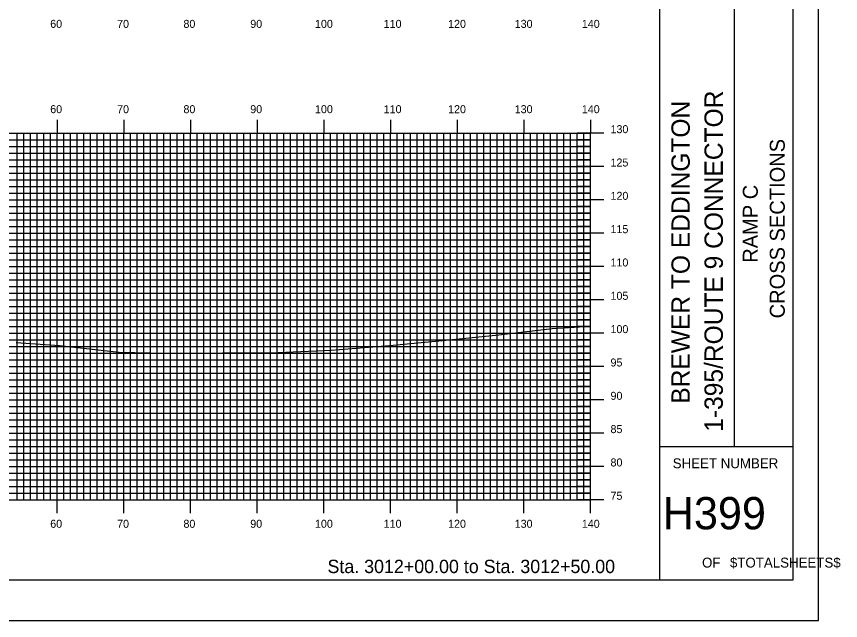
# Model space of a CAD drawing. Extents: x 1684012 to 1684355, y 461260 to 461480.
# Drawn here: x 1684231.6 to 1684355.2, y 461260 to 461350.6 of the extents above; entities that cross this region are included whole.
import ezdxf

# ---------------------------------------------------------------- set-up
doc = ezdxf.new("R2010")
doc.units = 0
for name, color, linetype in [('BORDER', 7, 'Continuous'), ('H_V ANNOTATION', 7, 'Continuous'), ('MAJOR', 7, 'Continuous'), ('MINOR', 7, 'Continuous'), ('PLOT BOUNDARY', 7, 'Continuous'), ('S_Roadway_Centerline', 7, 'Continuous')]:
    doc.layers.add(name, color=color, linetype=linetype)

msp = doc.modelspace()

# ---------------------------------------------------------------- linework, layer by layer
at = {"layer": 'BORDER'}
for p, q in [((1684328.09, 461266.07), (1684328.09, 461476.07)), ((1684339.27, 461286.08), (1684339.27, 461356.08)), ((1684328.09, 461286.08), (1684348.09, 461286.08))]:
    msp.add_line(p, q, dxfattribs=at)
msp.add_lwpolyline([(1684028.09, 461266.07), (1684348.09, 461266.07), (1684348.09, 461476.07), (1684028.09, 461476.07)], close=True, dxfattribs=at)
at = {"layer": 'MAJOR'}
for p, q in [((1684237.69, 461335.08), (1684237.69, 461333.07)), ((1684247.69, 461335.08), (1684247.69, 461333.07)), ((1684257.69, 461335.08), (1684257.69, 461333.07)), ((1684267.69, 461335.08), (1684267.69, 461333.07)), ((1684277.69, 461335.08), (1684277.69, 461333.07)), ((1684287.69, 461335.08), (1684287.69, 461333.07)), ((1684297.69, 461335.08), (1684297.69, 461333.07)), ((1684307.69, 461335.08), (1684307.69, 461333.07)), ((1684317.69, 461335.08), (1684317.69, 461333.07)), ((1684037.69, 461333.07), (1684317.69, 461333.07)), ((1684037.69, 461333.07), (1684317.69, 461333.07)), ((1684237.69, 461278.07), (1684237.69, 461333.07)), ((1684247.69, 461278.07), (1684247.69, 461333.07)), ((1684257.69, 461278.07), (1684257.69, 461333.07)), ((1684267.69, 461278.07), (1684267.69, 461333.07)), ((1684277.69, 461278.07), (1684277.69, 461333.07)), ((1684287.69, 461278.07), (1684287.69, 461333.07)), ((1684297.69, 461278.07), (1684297.69, 461333.07)), ((1684307.69, 461278.07), (1684307.69, 461333.07)), ((1684319.69, 461333.07), (1684315.69, 461333.07)), ((1684317.69, 461278.07), (1684317.69, 461333.07)), ((1684317.69, 461278.07), (1684317.69, 461333.07)), ((1684037.69, 461328.07), (1684317.69, 461328.07)), ((1684319.69, 461328.07), (1684315.69, 461328.07)), ((1684037.69, 461323.07), (1684317.69, 461323.07)), ((1684319.69, 461323.07), (1684315.69, 461323.07)), ((1684037.69, 461318.07), (1684317.69, 461318.07)), ((1684319.69, 461318.07), (1684315.69, 461318.07)), ((1684037.69, 461313.07), (1684317.69, 461313.07)), ((1684319.69, 461313.07), (1684315.69, 461313.07)), ((1684037.69, 461308.07), (1684317.69, 461308.07)), ((1684319.69, 461308.07), (1684315.69, 461308.07)), ((1684037.69, 461303.07), (1684317.69, 461303.07)), ((1684319.69, 461303.07), (1684315.69, 461303.07)), ((1684037.69, 461298.07), (1684317.69, 461298.07)), ((1684319.69, 461298.07), (1684315.69, 461298.07)), ((1684037.69, 461293.07), (1684317.69, 461293.07)), ((1684319.69, 461293.07), (1684315.69, 461293.07)), ((1684037.69, 461288.07), (1684317.69, 461288.07)), ((1684319.69, 461288.07), (1684315.69, 461288.07)), ((1684037.69, 461283.07), (1684317.69, 461283.07)), ((1684319.69, 461283.07), (1684315.69, 461283.07)), ((1684037.69, 461278.07), (1684317.69, 461278.07)), ((1684037.69, 461278.07), (1684317.69, 461278.07)), ((1684237.69, 461276.07), (1684237.69, 461278.07)), ((1684247.69, 461276.07), (1684247.69, 461278.07)), ((1684257.69, 461276.07), (1684257.69, 461278.07)), ((1684267.69, 461276.07), (1684267.69, 461278.07)), ((1684277.69, 461276.07), (1684277.69, 461278.07)), ((1684287.69, 461276.07), (1684287.69, 461278.07)), ((1684297.69, 461276.07), (1684297.69, 461278.07)), ((1684307.69, 461276.07), (1684307.69, 461278.07)), ((1684319.69, 461278.07), (1684315.69, 461278.07)), ((1684317.69, 461276.07), (1684317.69, 461278.07))]:
    msp.add_line(p, q, dxfattribs=at)
at = {"layer": 'MINOR'}
for p, q in [((1684231.69, 461278.07), (1684231.69, 461333.07)), ((1684232.69, 461278.07), (1684232.69, 461333.07)), ((1684233.69, 461278.07), (1684233.69, 461333.07)), ((1684234.69, 461278.07), (1684234.69, 461333.07)), ((1684235.69, 461278.07), (1684235.69, 461333.07)), ((1684236.69, 461278.07), (1684236.69, 461333.07)), ((1684238.69, 461278.07), (1684238.69, 461333.07)), ((1684239.69, 461278.07), (1684239.69, 461333.07)), ((1684240.69, 461278.07), (1684240.69, 461333.07)), ((1684241.69, 461278.07), (1684241.69, 461333.07)), ((1684242.69, 461278.07), (1684242.69, 461333.07)), ((1684243.69, 461278.07), (1684243.69, 461333.07)), ((1684244.69, 461278.07), (1684244.69, 461333.07)), ((1684245.69, 461278.07), (1684245.69, 461333.07)), ((1684246.69, 461278.07), (1684246.69, 461333.07)), ((1684248.69, 461278.07), (1684248.69, 461333.07)), ((1684249.69, 461278.07), (1684249.69, 461333.07)), ((1684250.69, 461278.07), (1684250.69, 461333.07)), ((1684251.69, 461278.07), (1684251.69, 461333.07)), ((1684252.69, 461278.07), (1684252.69, 461333.07)), ((1684253.69, 461278.07), (1684253.69, 461333.07)), ((1684254.69, 461278.07), (1684254.69, 461333.07)), ((1684255.69, 461278.07), (1684255.69, 461333.07)), ((1684256.69, 461278.07), (1684256.69, 461333.07)), ((1684258.69, 461278.07), (1684258.69, 461333.07)), ((1684259.69, 461278.07), (1684259.69, 461333.07)), ((1684260.69, 461278.07), (1684260.69, 461333.07)), ((1684261.69, 461278.07), (1684261.69, 461333.07)), ((1684262.69, 461278.07), (1684262.69, 461333.07)), ((1684263.69, 461278.07), (1684263.69, 461333.07)), ((1684264.69, 461278.07), (1684264.69, 461333.07)), ((1684265.69, 461278.07), (1684265.69, 461333.07)), ((1684266.69, 461278.07), (1684266.69, 461333.07)), ((1684268.69, 461278.07), (1684268.69, 461333.07)), ((1684269.69, 461278.07), (1684269.69, 461333.07)), ((1684270.69, 461278.07), (1684270.69, 461333.07)), ((1684271.69, 461278.07), (1684271.69, 461333.07)), ((1684272.69, 461278.07), (1684272.69, 461333.07)), ((1684273.69, 461278.07), (1684273.69, 461333.07)), ((1684274.69, 461278.07), (1684274.69, 461333.07)), ((1684275.69, 461278.07), (1684275.69, 461333.07)), ((1684276.69, 461278.07), (1684276.69, 461333.07)), ((1684278.69, 461278.07), (1684278.69, 461333.07)), ((1684279.69, 461278.07), (1684279.69, 461333.07)), ((1684280.69, 461278.07), (1684280.69, 461333.07)), ((1684281.69, 461278.07), (1684281.69, 461333.07)), ((1684282.69, 461278.07), (1684282.69, 461333.07)), ((1684283.69, 461278.07), (1684283.69, 461333.07)), ((1684284.69, 461278.07), (1684284.69, 461333.07)), ((1684285.69, 461278.07), (1684285.69, 461333.07)), ((1684286.69, 461278.07), (1684286.69, 461333.07)), ((1684288.69, 461278.07), (1684288.69, 461333.07)), ((1684289.69, 461278.07), (1684289.69, 461333.07)), ((1684290.69, 461278.07), (1684290.69, 461333.07)), ((1684291.69, 461278.07), (1684291.69, 461333.07)), ((1684292.69, 461278.07), (1684292.69, 461333.07)), ((1684293.69, 461278.07), (1684293.69, 461333.07)), ((1684294.69, 461278.07), (1684294.69, 461333.07)), ((1684295.69, 461278.07), (1684295.69, 461333.07)), ((1684296.69, 461278.07), (1684296.69, 461333.07)), ((1684298.69, 461278.07), (1684298.69, 461333.07)), ((1684299.69, 461278.07), (1684299.69, 461333.07)), ((1684300.69, 461278.07), (1684300.69, 461333.07)), ((1684301.69, 461278.07), (1684301.69, 461333.07)), ((1684302.69, 461278.07), (1684302.69, 461333.07)), ((1684303.69, 461278.07), (1684303.69, 461333.07)), ((1684304.69, 461278.07), (1684304.69, 461333.07)), ((1684305.69, 461278.07), (1684305.69, 461333.07)), ((1684306.69, 461278.07), (1684306.69, 461333.07)), ((1684308.69, 461278.07), (1684308.69, 461333.07)), ((1684309.69, 461278.07), (1684309.69, 461333.07)), ((1684310.69, 461278.07), (1684310.69, 461333.07)), ((1684311.69, 461278.07), (1684311.69, 461333.07)), ((1684312.69, 461278.07), (1684312.69, 461333.07)), ((1684313.69, 461278.07), (1684313.69, 461333.07)), ((1684314.69, 461278.07), (1684314.69, 461333.07)), ((1684315.69, 461278.07), (1684315.69, 461333.07)), ((1684316.69, 461278.07), (1684316.69, 461333.07)), ((1684037.69, 461332.07), (1684317.69, 461332.07)), ((1684317.69, 461332.07), (1684315.69, 461332.07)), ((1684037.69, 461331.07), (1684317.69, 461331.07)), ((1684317.69, 461331.07), (1684315.69, 461331.07)), ((1684037.69, 461330.07), (1684317.69, 461330.07)), ((1684317.69, 461330.07), (1684315.69, 461330.07)), ((1684037.69, 461329.07), (1684317.69, 461329.07)), ((1684317.69, 461329.07), (1684315.69, 461329.07)), ((1684037.69, 461327.07), (1684317.69, 461327.07)), ((1684317.69, 461327.07), (1684315.69, 461327.07)), ((1684037.69, 461326.07), (1684317.69, 461326.07)), ((1684317.69, 461326.07), (1684315.69, 461326.07)), ((1684037.69, 461325.07), (1684317.69, 461325.07)), ((1684317.69, 461325.07), (1684315.69, 461325.07)), ((1684037.69, 461324.07), (1684317.69, 461324.07)), ((1684317.69, 461324.07), (1684315.69, 461324.07)), ((1684037.69, 461322.07), (1684317.69, 461322.07)), ((1684317.69, 461322.07), (1684315.69, 461322.07)), ((1684037.69, 461321.07), (1684317.69, 461321.07)), ((1684317.69, 461321.07), (1684315.69, 461321.07)), ((1684037.69, 461320.07), (1684317.69, 461320.07)), ((1684317.69, 461320.07), (1684315.69, 461320.07)), ((1684037.69, 461319.07), (1684317.69, 461319.07)), ((1684317.69, 461319.07), (1684315.69, 461319.07)), ((1684037.69, 461317.07), (1684317.69, 461317.07)), ((1684317.69, 461317.07), (1684315.69, 461317.07)), ((1684037.69, 461316.07), (1684317.69, 461316.07)), ((1684317.69, 461316.07), (1684315.69, 461316.07)), ((1684037.69, 461315.07), (1684317.69, 461315.07)), ((1684317.69, 461315.07), (1684315.69, 461315.07)), ((1684037.69, 461314.07), (1684317.69, 461314.07)), ((1684317.69, 461314.07), (1684315.69, 461314.07)), ((1684037.69, 461312.07), (1684317.69, 461312.07)), ((1684317.69, 461312.07), (1684315.69, 461312.07)), ((1684037.69, 461311.07), (1684317.69, 461311.07)), ((1684317.69, 461311.07), (1684315.69, 461311.07)), ((1684037.69, 461310.07), (1684317.69, 461310.07)), ((1684317.69, 461310.07), (1684315.69, 461310.07)), ((1684037.69, 461309.07), (1684317.69, 461309.07)), ((1684317.69, 461309.07), (1684315.69, 461309.07)), ((1684037.69, 461307.07), (1684317.69, 461307.07)), ((1684317.69, 461307.07), (1684315.69, 461307.07)), ((1684037.69, 461306.07), (1684317.69, 461306.07)), ((1684317.69, 461306.07), (1684315.69, 461306.07)), ((1684037.69, 461305.07), (1684317.69, 461305.07)), ((1684317.69, 461305.07), (1684315.69, 461305.07)), ((1684037.69, 461304.07), (1684317.69, 461304.07)), ((1684317.69, 461304.07), (1684315.69, 461304.07)), ((1684037.69, 461302.07), (1684317.69, 461302.07)), ((1684317.69, 461302.07), (1684315.69, 461302.07)), ((1684037.69, 461301.07), (1684317.69, 461301.07)), ((1684317.69, 461301.07), (1684315.69, 461301.07)), ((1684037.69, 461300.07), (1684317.69, 461300.07)), ((1684317.69, 461300.07), (1684315.69, 461300.07)), ((1684037.69, 461299.07), (1684317.69, 461299.07)), ((1684317.69, 461299.07), (1684315.69, 461299.07)), ((1684037.69, 461297.07), (1684317.69, 461297.07)), ((1684317.69, 461297.07), (1684315.69, 461297.07)), ((1684037.69, 461296.07), (1684317.69, 461296.07)), ((1684317.69, 461296.07), (1684315.69, 461296.07)), ((1684037.69, 461295.07), (1684317.69, 461295.07)), ((1684317.69, 461295.07), (1684315.69, 461295.07)), ((1684037.69, 461294.07), (1684317.69, 461294.07)), ((1684317.69, 461294.07), (1684315.69, 461294.07)), ((1684037.69, 461292.07), (1684317.69, 461292.07)), ((1684317.69, 461292.07), (1684315.69, 461292.07)), ((1684037.69, 461291.07), (1684317.69, 461291.07)), ((1684317.69, 461291.07), (1684315.69, 461291.07)), ((1684037.69, 461290.07), (1684317.69, 461290.07)), ((1684317.69, 461290.07), (1684315.69, 461290.07)), ((1684037.69, 461289.07), (1684317.69, 461289.07)), ((1684317.69, 461289.07), (1684315.69, 461289.07)), ((1684037.69, 461287.07), (1684317.69, 461287.07)), ((1684037.69, 461286.07), (1684317.69, 461286.07)), ((1684317.69, 461287.07), (1684315.69, 461287.07)), ((1684317.69, 461286.07), (1684315.69, 461286.07)), ((1684037.69, 461285.07), (1684317.69, 461285.07)), ((1684317.69, 461285.07), (1684315.69, 461285.07)), ((1684037.69, 461284.07), (1684317.69, 461284.07)), ((1684317.69, 461284.07), (1684315.69, 461284.07)), ((1684037.69, 461282.07), (1684317.69, 461282.07)), ((1684037.69, 461281.07), (1684317.69, 461281.07)), ((1684317.69, 461282.07), (1684315.69, 461282.07)), ((1684317.69, 461281.07), (1684315.69, 461281.07)), ((1684037.69, 461280.07), (1684317.69, 461280.07)), ((1684317.69, 461280.07), (1684315.69, 461280.07)), ((1684037.69, 461279.07), (1684317.69, 461279.07)), ((1684317.69, 461279.07), (1684315.69, 461279.07))]:
    msp.add_line(p, q, dxfattribs=at)
at = {"layer": 'PLOT BOUNDARY'}
msp.add_lwpolyline([(1684011.9, 461259.95), (1684351.9, 461259.95), (1684351.9, 461479.95), (1684011.9, 461479.95)], close=True, dxfattribs=at)
at = {"layer": 'S_Roadway_Centerline'}
msp.add_lwpolyline([(1684231.55, 461301.69), (1684238.06, 461301.23), (1684247, 461300.2), (1684254.09, 461300.06), (1684270.86, 461300.18), (1684278.81, 461300.54), (1684287.56, 461301.24), (1684295.47, 461301.96), (1684303.94, 461302.82), (1684311.93, 461303.77), (1684317.69, 461304.11)], dxfattribs=at)

# ---------------------------------------------------------------- texts
at = {"layer": 'BORDER'}
for s, height, p in [('1-395/ROUTE 9 CONNECTOR', 2.7557, (1684337.54, 461288.27)), ('BREWER TO EDDINGTON', 2.7557, (1684332.58, 461292.48)), ('CROSS SECTIONS', 2.25, (1684346.83, 461305.29)), ('RAMP C', 2.25, (1684342.78, 461313.63))]:
    msp.add_text(s, height=height, rotation=90, dxfattribs=at).set_placement(p)
for s, height, p in [('SHEET NUMBER', 1.4905, (1684330.02, 461282.8)), ('H399', 4.839, (1684328.53, 461273.64)), ('OF', 1.491, (1684334.42, 461267.9)), ('$TOTALSHEETS$', 1.4905, (1684338.6, 461267.9))]:
    msp.add_text(s, height=height, dxfattribs=at).set_placement(p)
at = {"layer": 'H_V ANNOTATION'}
for s, height, p in [('60', 1.2, (1684236.66, 461348.87)), ('70', 1.2, (1684246.69, 461348.87)), ('80', 1.2, (1684256.64, 461348.87)), ('90', 1.2, (1684266.66, 461348.87)), ('100', 1.2, (1684276.37, 461348.87)), ('110', 1.2, (1684286.67, 461348.87)), ('120', 1.2, (1684296.33, 461348.87)), ('130', 1.2, (1684306.32, 461348.87)), ('140', 1.2, (1684316.39, 461348.87)), ('60', 1.2, (1684236.66, 461336.07)), ('70', 1.2, (1684246.69, 461336.07)), ('80', 1.2, (1684256.64, 461336.07)), ('90', 1.2, (1684266.66, 461336.07)), ('100', 1.2, (1684276.37, 461336.07)), ('110', 1.2, (1684286.67, 461336.07)), ('120', 1.2, (1684296.33, 461336.07)), ('130', 1.2, (1684306.32, 461336.07)), ('140', 1.2, (1684316.39, 461336.07)), ('130', 1.2, (1684320.69, 461333.07)), ('125', 1.2, (1684320.69, 461328.07)), ('120', 1.2, (1684320.69, 461323.07)), ('115', 1.2, (1684320.69, 461318.07)), ('110', 1.2, (1684320.69, 461313.07)), ('105', 1.2, (1684320.69, 461308.07)), ('100', 1.2, (1684320.69, 461303.07)), ('95', 1.2, (1684320.69, 461298.07)), ('90', 1.2, (1684320.69, 461293.07)), ('85', 1.2, (1684320.69, 461288.07)), ('80', 1.2, (1684320.69, 461283.07)), ('75', 1.2, (1684320.69, 461278.07)), ('60', 1.2, (1684236.66, 461273.87)), ('70', 1.2, (1684246.69, 461273.87)), ('80', 1.2, (1684256.64, 461273.87)), ('90', 1.2, (1684266.66, 461273.87)), ('100', 1.2, (1684276.37, 461273.87)), ('110', 1.2, (1684286.67, 461273.87)), ('120', 1.2, (1684296.33, 461273.87)), ('130', 1.2, (1684306.32, 461273.87)), ('140', 1.2, (1684316.39, 461273.87)), ('Sta. 3012+00.00 to Sta. 3012+50.00', 2.0004, (1684278.24, 461267.07))]:
    msp.add_text(s, height=height, dxfattribs=at).set_placement(p)

doc.saveas('drawing.dxf')
